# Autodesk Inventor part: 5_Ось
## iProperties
Created: 2009-12
Part Number: 5_Ось
Document SubType Name: Modeling
Designer: Jeck
Density: 1 g/cm^3
Mass: 151.033 g
Surface Area: 197.9 cm^2
Volume: 151.033 cm^3
Author: Jeck
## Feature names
1. Выдавливание1 [Extrusion]
2. Выдавливание2 [Extrusion]
3. Фаска2 [Chamfer]
